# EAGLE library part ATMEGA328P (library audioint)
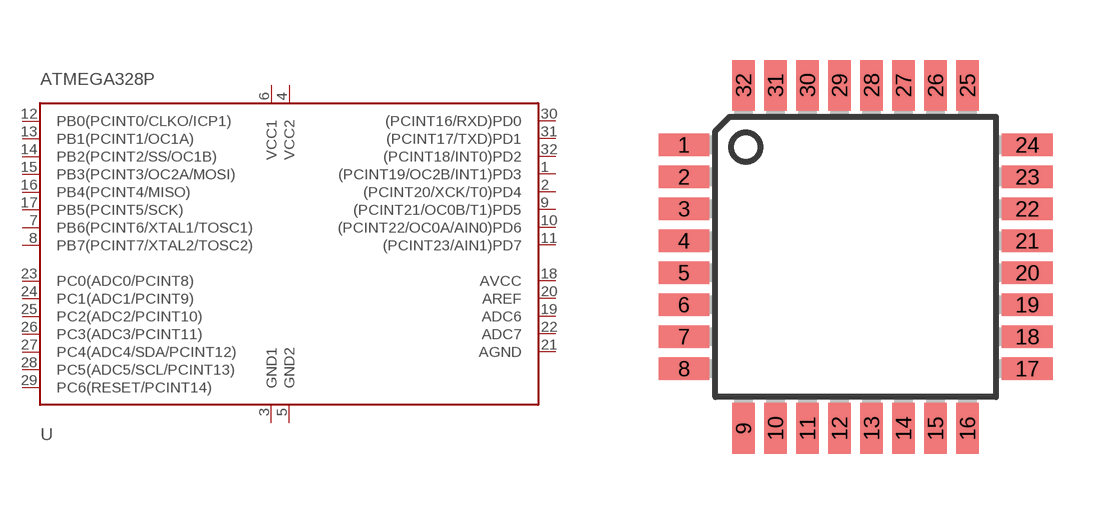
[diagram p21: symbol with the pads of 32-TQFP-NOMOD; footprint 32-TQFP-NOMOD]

Designator prefix -

## ATMEGA328P  [32-TQFP-NOMOD]
1  (PCINT19/OC2B/INT1)PD3
2  (PCINT20/XCK/T0)PD4
3  GND1
4  VCC2
5  GND2
6  VCC1
7  PB6(PCINT6/XTAL1/TOSC1)
8  PB7(PCINT7/XTAL2/TOSC2)
9  (PCINT21/OC0B/T1)PD5
10  (PCINT22/OC0A/AIN0)PD6
11  (PCINT23/AIN1)PD7
12  PB0(PCINT0/CLKO/ICP1)
13  PB1(PCINT1/OC1A)
14  PB2(PCINT2/SS/OC1B)
15  PB3(PCINT3/OC2A/MOSI)
16  PB4(PCINT4/MISO)
17  PB5(PCINT5/SCK)
18  AVCC
19  ADC6
20  AREF
21  AGND
22  ADC7
23  PC0(ADC0/PCINT8)
24  PC1(ADC1/PCINT9)
25  PC2(ADC2/PCINT10)
26  PC3(ADC3/PCINT11)
27  PC4(ADC4/SDA/PCINT12)
28  PC5(ADC5/SCL/PCINT13)
29  PC6(RESET/PCINT14)
30  (PCINT16/RXD)PD0
31  (PCINT17/TXD)PD1
32  (PCINT18/INT0)PD2

## Footprint 32-TQFP-NOMOD (pad centres in mm)
smd 1.27 x 0.559: 1 -4.293,2.8; 2 -4.293,2; 3 -4.293,1.2; 4 -4.293,0.4; 5 -4.293,-0.4; 6 -4.293,-1.2; 7 -4.293,-2; 8 -4.293,-2.8; 17 4.293,-2.8; 18 4.293,-2; 19 4.293,-1.2; 20 4.293,-0.4; 21 4.293,0.4; 22 4.293,1.2; 23 4.293,2; 24 4.293,2.8
smd 0.559 x 1.27: 9 -2.8,-4.293; 10 -2,-4.293; 11 -1.2,-4.293; 12 -0.4,-4.293; 13 0.4,-4.293; 14 1.2,-4.293; 15 2,-4.293; 16 2.8,-4.293; 25 2.8,4.293; 26 2,4.293; 27 1.2,4.293; 28 0.4,4.293; 29 -0.4,4.293; 30 -1.2,4.293; 31 -2,4.293; 32 -2.8,4.293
